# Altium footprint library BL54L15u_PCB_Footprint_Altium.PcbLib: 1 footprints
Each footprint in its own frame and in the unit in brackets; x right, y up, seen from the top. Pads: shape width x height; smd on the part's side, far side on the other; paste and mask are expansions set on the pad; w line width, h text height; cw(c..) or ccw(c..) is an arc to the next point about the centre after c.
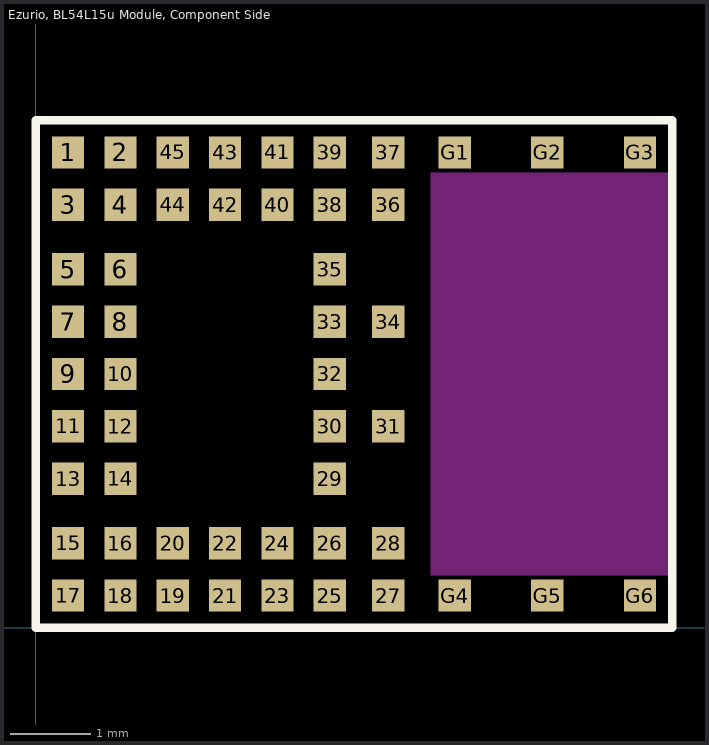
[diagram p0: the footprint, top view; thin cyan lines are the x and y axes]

## Ezurio, BL54L15u Module, Component Side [mm] "Ezurio, BL54L15u Module, Component Side"
height 1.75
pads (51):
  rect 0.4x0.4 smd paste+0 mask+0.051: 1(0.4,5.9) 2(1.05,5.9) 3(0.4,5.25) 4(1.05,5.25) 5(0.4,4.45) 6(1.05,4.45) 7(0.4,3.8) 8(1.05,3.8) 9(0.4,3.15) 10(1.05,3.15) 11(0.4,2.5) 12(1.05,2.5) 13(0.4,1.85) 14(1.05,1.85) 15(0.4,1.05) 16(1.05,1.05) 17(0.4,0.4) 18(1.05,0.4) 19(1.7,0.4) 20(1.7,1.05) 21(2.35,0.4) 22(2.35,1.05) 23(3,0.4) 24(3,1.05) 25(3.65,0.4) 26(3.65,1.05) 27(4.375,0.4) 28(4.375,1.05) 29(3.65,1.85) 30(3.65,2.5) 31(4.375,2.5) 32(3.65,3.15) 33(3.65,3.8) 34(4.375,3.8) 35(3.65,4.45) 36(4.375,5.25) 37(4.375,5.9) 38(3.65,5.25) 39(3.65,5.9) 40(3,5.25) 41(3,5.9) 42(2.35,5.25) 43(2.35,5.9) 44(1.7,5.25) 45(1.7,5.9) G1(5.2,5.9) G2(6.35,5.9) G3(7.5,5.9) G4(5.2,0.4) G5(6.35,0.4) G6(7.5,0.4)
Top Overlay:
  lines w0.102: 0,6.3 0,0 7.9,0 7.9,6.3 0,6.3
Keep-Out Layer:
  region: 4.9,5.65 4.9,0.65 7.9,0.65 7.9,5.65
Mechanical 13:
  lines w0.025: 0,6.3 0,0 7.9,0 7.9,6.3 0,6.3
  text ".Designator" at 0.09,6.632 h0.76
3D body: height 0.01, standoff 0, extent 0.85,1.65 1.25,2.05
3D body: height 0.01, standoff 0, extent 0.85,2.3 1.25,2.7
3D body: height 0.01, standoff 0, extent 0.85,2.95 1.25,3.35
3D body: height 0.01, standoff 0, extent 0.85,3.6 1.25,4
3D body: height 0.01, standoff 0, extent 0.85,4.25 1.25,4.65
3D body: height 0.01, standoff 0, extent 7.3,0.2 7.7,0.6
3D body: height 0.01, standoff 0, extent 6.15,0.2 6.55,0.6
3D body: height 0.01, standoff 0, extent 5,0.2 5.4,0.6
3D body: height 0.01, standoff 0, extent 5,5.7 5.4,6.1
3D body: height 0.01, standoff 0, extent 7.3,5.7 7.7,6.1
3D body: height 0.01, standoff 0, extent 6.15,5.7 6.55,6.1
3D body: height 0.01, standoff 0, extent 4.175,0.2 4.575,0.6
3D body: height 0.01, standoff 0, extent 3.45,0.2 3.85,0.6
3D body: height 0.01, standoff 0, extent 2.8,0.2 3.2,0.6
3D body: height 0.01, standoff 0, extent 2.15,0.2 2.55,0.6
3D body: height 0.01, standoff 0, extent 1.5,0.2 1.9,0.6
3D body: height 0.01, standoff 0, extent 0.85,0.2 1.25,0.6
3D body: height 0.01, standoff 0, extent 0.2,0.2 0.6,0.6
3D body: height 0.01, standoff 0, extent 3.45,0.85 3.85,1.25
3D body: height 0.01, standoff 0, extent 2.8,0.85 3.2,1.25
3D body: height 0.01, standoff 0, extent 2.15,0.85 2.55,1.25
3D body: height 0.01, standoff 0, extent 1.5,0.85 1.9,1.25
3D body: height 0.01, standoff 0, extent 0.85,0.85 1.25,1.25
3D body: height 0.01, standoff 0, extent 0.2,0.85 0.6,1.25
3D body: height 0.01, standoff 0, extent 3.45,1.65 3.85,2.05
3D body: height 0.01, standoff 0, extent 0.2,1.65 0.6,2.05
3D body: height 0.01, standoff 0, extent 3.45,2.3 3.85,2.7
3D body: height 0.01, standoff 0, extent 0.2,2.3 0.6,2.7
3D body: height 0.01, standoff 0, extent 3.45,2.95 3.85,3.35
3D body: height 0.01, standoff 0, extent 0.2,2.95 0.6,3.35
3D body: height 0.01, standoff 0, extent 3.45,3.6 3.85,4
3D body: height 0.01, standoff 0, extent 0.2,3.6 0.6,4
3D body: height 0.01, standoff 0, extent 3.45,4.25 3.85,4.65
3D body: height 0.01, standoff 0, extent 0.2,4.25 0.6,4.65
3D body: height 0.01, standoff 0, extent 3.45,5.05 3.85,5.45
3D body: height 0.01, standoff 0, extent 2.8,5.05 3.2,5.45
3D body: height 0.01, standoff 0, extent 2.15,5.05 2.55,5.45
3D body: height 0.01, standoff 0, extent 1.5,5.05 1.9,5.45
3D body: height 0.01, standoff 0, extent 0.85,5.05 1.25,5.45
3D body: height 0.01, standoff 0, extent 0.2,5.05 0.6,5.45
3D body: height 0.01, standoff 0, extent 0.2,5.7 0.6,6.1
3D body: height 0.01, standoff 0, extent 0.85,5.7 1.25,6.1
3D body: height 0.01, standoff 0, extent 1.5,5.7 1.9,6.1
3D body: height 0.01, standoff 0, extent 2.15,5.7 2.55,6.1
3D body: height 0.01, standoff 0, extent 2.8,5.7 3.2,6.1
3D body: height 0.01, standoff 0, extent 3.45,5.7 3.85,6.1
3D body: height 0.01, standoff 0, extent 4.175,5.7 4.575,6.1
3D body: height 0.01, standoff 0, extent 4.175,5.05 4.575,5.45
3D body: height 0.01, standoff 0, extent 4.175,3.6 4.575,4
3D body: height 0.01, standoff 0, extent 4.175,2.3 4.575,2.7
3D body: height 0.01, standoff 0, extent 4.175,0.85 4.575,1.25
